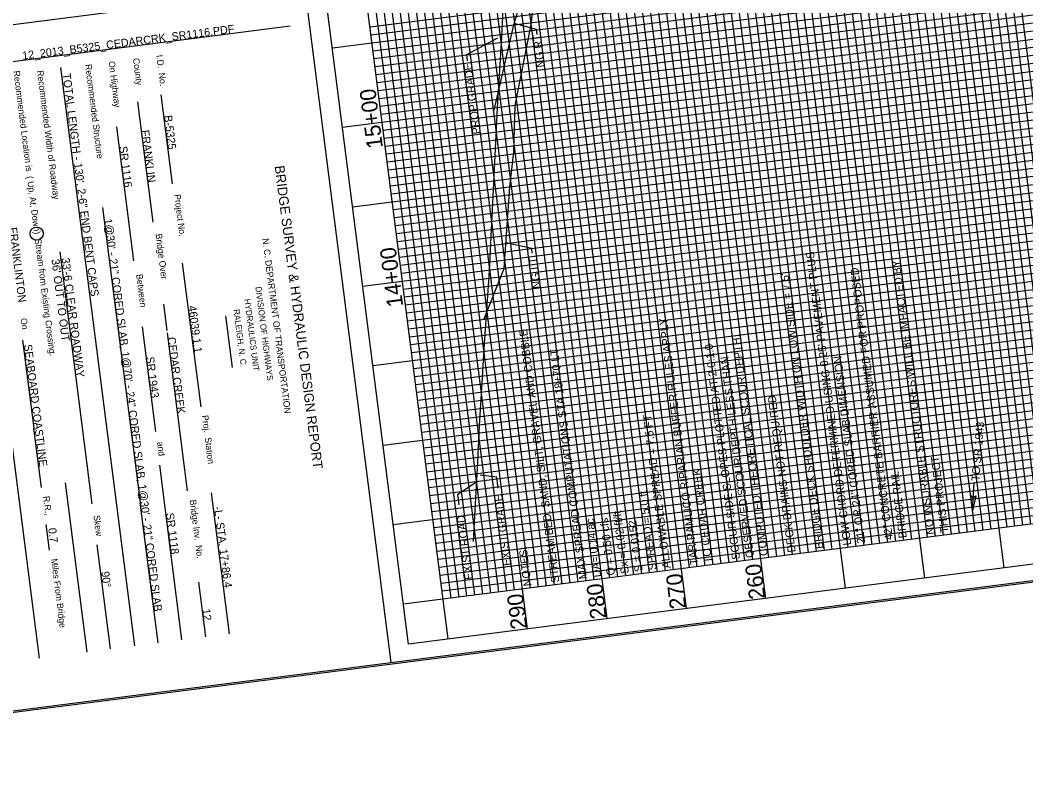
# Model space of a CAD drawing. Extents: x 2166991 to 2168413, y 842679 to 844296.
# Drawn here: x 2167468 to 2168096, y 842679 to 843150 of the extents above; entities that cross this region are included whole.
import ezdxf

# ---------------------------------------------------------------- set-up
doc = ezdxf.new("R2010")
doc.units = 0
for name, color, linetype in [('Exist Horizontal Alignment', 7, 'Continuous'), ('Exist Hydrographic Natural Ground Left', 7, 'Continuous'), ('Exist Hydrographic Natural Ground Right', 7, 'Continuous'), ('Old_Level_46', 7, 'Continuous'), ('Old_Level_61', 7, 'Continuous'), ('Prop Plan Preparation Cover Label', 7, 'Continuous'), ('Prop Plan Preparation Elevation Label', 7, 'Continuous'), ('Prop Plan Preparation Sheet Bridge Report Limited Study CELL', 7, 'Continuous'), ('Prop Plan Preparation Station Label', 7, 'Continuous'), ('Prop Plan Preparation Table Performance Curve CELL', 7, 'Continuous'), ('Sheet Plot Border Outside CELL', 7, 'Continuous'), ('Typical Terminator CELL', 7, 'Continuous')]:
    doc.layers.add(name, color=color, linetype=linetype)

msp = doc.modelspace()

# ---------------------------------------------------------------- linework, layer by layer
at = {"layer": 'Exist Horizontal Alignment'}
msp.add_lwpolyline([(2167751.39, 842824.91), (2167752.39, 842844.74), (2167753.95, 842874.72), (2167755.15, 842897.27), (2167757.06, 842927.31), (2167757.92, 842945.41), (2167760.09, 842975.47), (2167761.25, 842993.97), (2167762.76, 843023.98), (2167763.76, 843044.55), (2167765.23, 843074.51), (2167766.29, 843095.78), (2167768.15, 843125.8), (2167769.02, 843139.96), (2167770.48, 843169.95), (2167771.39, 843188.46), (2167770.67, 843218.15), (2167770.25, 843236.07), (2167768.33, 843265.68), (2167767.02, 843285.86), (2167763.97, 843315.19), (2167760.56, 843343.94)], dxfattribs=at)
at = {"layer": 'Exist Hydrographic Natural Ground Left'}
msp.add_lwpolyline([(2167757.79, 842963.56), (2167770.55, 842995.45), (2167773.98, 843046.3), (2167776.61, 843068.3), (2167777.35, 843097.13), (2167787.62, 843148.85), (2167792.18, 843199.84), (2167793.61, 843214.01), (2167797.76, 843250.96), (2167815.06, 843303.58), (2167817.99, 843332.01), (2167815.17, 843366.59)], dxfattribs=at)
at = {"layer": 'Exist Hydrographic Natural Ground Right'}
msp.add_lwpolyline([(2167764.31, 843094.3), (2167776.57, 843147.44), (2167792.18, 843199.84), (2167810.26, 843216.13), (2167772.9, 843247.78)], dxfattribs=at)
at = {"layer": 'Old_Level_46'}
for points in [[(2167791.01, 843141.49), (2167790.62, 843144.55), (2167776.78, 843148.24)], [(2167747.61, 843125.02), (2167747.11, 843128.93), (2167766.47, 843139.45)], [(2167788.04, 843005.03), (2167787.67, 843007.92), (2167771.61, 843011.4)], [(2167742.33, 842847.83), (2167741.48, 842854.49), (2167753.3, 842862.19)], [(2167766.83, 842858.38), (2167765.98, 842865.05), (2167755.49, 842866.42)]]:
    msp.add_lwpolyline(points, dxfattribs=at)
at = {"layer": 'Old_Level_61'}
msp.add_line((2168062.86, 842844.16), (2168064.07, 842861.57), dxfattribs=at)
at = {"layer": 'Prop Plan Preparation Cover Label'}
msp.add_circle((2167478.55, 843017.15), 4.12, dxfattribs=at)
at = {"layer": 'Prop Plan Preparation Sheet Bridge Report Limited Study CELL'}
for p, q in [((2168132.34, 842814.84), (2167973.96, 844054.76)), ((2168082.74, 842808.5), (2167924.37, 844048.43)), ((2168033.15, 842802.17), (2167874.77, 844042.09)), ((2167983.55, 842795.83), (2167825.17, 844035.76)), ((2167933.95, 842789.5), (2167775.57, 844029.42)), ((2168124.21, 842839), (2167972.17, 844029.33)), ((2168134.13, 842840.27), (2167982.09, 844030.6)), ((2167884.35, 842783.16), (2167725.98, 844023.09)), ((2168074.61, 842832.67), (2167922.57, 844023)), ((2168084.53, 842833.93), (2167932.49, 844024.26)), ((2168089.49, 842834.57), (2167937.45, 844024.9)), ((2168094.45, 842835.2), (2167942.41, 844025.53)), ((2168099.41, 842835.83), (2167947.37, 844026.16)), ((2168104.37, 842836.47), (2167952.33, 844026.8)), ((2168109.33, 842837.1), (2167957.29, 844027.43)), ((2168114.29, 842837.73), (2167962.25, 844028.06)), ((2168119.25, 842838.37), (2167967.21, 844028.7)), ((2167834.76, 842776.83), (2167676.38, 844016.75)), ((2168025.02, 842826.33), (2167872.98, 844016.66)), ((2168034.94, 842827.6), (2167882.9, 844017.93)), ((2168039.9, 842828.23), (2167887.86, 844018.56)), ((2168044.86, 842828.87), (2167892.82, 844019.19)), ((2168049.82, 842829.5), (2167897.78, 844019.83)), ((2168054.78, 842830.13), (2167902.74, 844020.46)), ((2168059.74, 842830.77), (2167907.69, 844021.1)), ((2168064.7, 842831.4), (2167912.65, 844021.73)), ((2168069.66, 842832.03), (2167917.61, 844022.36)), ((2167538.09, 844014.21), (2167699.63, 842749.49)), ((2167538.09, 844014.21), (2167699.63, 842749.49)), ((2167785.16, 842770.49), (2167626.78, 844010.42)), ((2167985.34, 842821.26), (2167833.3, 844011.59)), ((2167990.3, 842821.9), (2167838.26, 844012.23)), ((2167995.26, 842822.53), (2167843.22, 844012.86)), ((2168000.22, 842823.16), (2167848.18, 844013.49)), ((2168005.18, 842823.8), (2167853.14, 844014.13)), ((2168010.14, 842824.43), (2167858.1, 844014.76)), ((2168015.1, 842825.06), (2167863.06, 844015.39)), ((2168020.06, 842825.7), (2167868.02, 844016.03)), ((2167935.74, 842814.93), (2167783.7, 844005.26)), ((2167940.7, 842815.56), (2167788.66, 844005.89)), ((2167945.66, 842816.2), (2167793.62, 844006.52)), ((2167950.62, 842816.83), (2167798.58, 844007.16)), ((2167955.58, 842817.46), (2167803.54, 844007.79)), ((2167960.54, 842818.1), (2167808.5, 844008.43)), ((2167965.5, 842818.73), (2167813.46, 844009.06)), ((2167970.46, 842819.36), (2167818.42, 844009.69)), ((2167975.42, 842820), (2167823.38, 844010.33)), ((2167710.76, 842760.99), (2167552.39, 844000.92)), ((2167735.56, 842764.16), (2167577.19, 844004.08)), ((2167886.15, 842808.59), (2167734.11, 843998.92)), ((2167891.11, 842809.23), (2167739.06, 843999.56)), ((2167896.07, 842809.86), (2167744.02, 844000.19)), ((2167901.03, 842810.49), (2167748.98, 844000.82)), ((2167905.98, 842811.13), (2167753.94, 844001.46)), ((2167910.94, 842811.76), (2167758.9, 844002.09)), ((2167915.9, 842812.39), (2167763.86, 844002.72)), ((2167920.86, 842813.03), (2167768.82, 844003.36)), ((2167925.82, 842813.66), (2167773.78, 844003.99)), ((2167836.55, 842802.26), (2167684.51, 843992.59)), ((2167841.51, 842802.89), (2167689.47, 843993.22)), ((2167846.47, 842803.53), (2167694.43, 843993.85)), ((2167851.43, 842804.16), (2167699.39, 843994.49)), ((2167856.39, 842804.79), (2167704.35, 843995.12)), ((2167861.35, 842805.43), (2167709.31, 843995.76)), ((2167866.31, 842806.06), (2167714.27, 843996.39)), ((2167871.27, 842806.69), (2167719.23, 843997.02)), ((2167876.23, 842807.33), (2167724.19, 843997.66)), ((2167786.95, 842795.92), (2167634.91, 843986.25)), ((2167791.91, 842796.56), (2167639.87, 843986.89)), ((2167796.87, 842797.19), (2167644.83, 843987.52)), ((2167801.83, 842797.82), (2167649.79, 843988.15)), ((2167806.79, 842798.46), (2167654.75, 843988.79)), ((2167811.75, 842799.09), (2167659.71, 843989.42)), ((2167816.71, 842799.72), (2167664.67, 843990.05)), ((2167821.67, 842800.36), (2167669.63, 843990.69)), ((2167826.63, 842800.99), (2167674.59, 843991.32)), ((2167737.35, 842789.59), (2167585.31, 843979.92)), ((2167742.31, 842790.22), (2167590.27, 843980.55)), ((2167747.27, 842790.86), (2167595.23, 843981.18)), ((2167752.23, 842791.49), (2167600.19, 843981.82)), ((2167757.19, 842792.12), (2167605.15, 843982.45)), ((2167762.15, 842792.76), (2167610.11, 843983.09)), ((2167767.11, 842793.39), (2167615.07, 843983.72)), ((2167772.07, 842794.02), (2167620.03, 843984.35)), ((2167777.03, 842794.66), (2167624.99, 843984.99)), ((2168182.75, 843209.4), (2167686.78, 843146.05)), ((2168183.39, 843204.44), (2167687.42, 843141.09)), ((2168184.02, 843199.48), (2167663.25, 843132.97)), ((2168184.65, 843194.53), (2167688.68, 843131.17)), ((2168185.29, 843189.57), (2167689.32, 843126.21)), ((2168185.92, 843184.61), (2167689.95, 843121.26)), ((2168186.55, 843179.65), (2167690.58, 843116.3)), ((2167100.22, 843101.38), (2167645.78, 843171.06)), ((2168187.19, 843174.69), (2167691.22, 843111.34)), ((2168187.82, 843169.73), (2167691.85, 843106.38)), ((2168188.45, 843164.77), (2167692.48, 843101.42)), ((2168189.09, 843159.81), (2167693.12, 843096.46)), ((2168189.72, 843154.85), (2167693.75, 843091.5)), ((2167458.71, 843124.09), (2167636.89, 843146.84)), ((2168190.36, 843149.89), (2167669.59, 843083.37)), ((2168190.99, 843144.93), (2167695.02, 843081.58)), ((2168191.62, 843139.97), (2167695.65, 843076.62)), ((2168192.26, 843135.01), (2167696.29, 843071.66)), ((2168192.89, 843130.05), (2167696.92, 843066.7)), ((2168193.52, 843125.09), (2167697.55, 843061.74)), ((2167493.43, 843120.82), (2167539.55, 842759.79)), ((2168194.16, 843120.13), (2167698.19, 843056.78)), ((2168194.79, 843115.17), (2167698.82, 843051.82)), ((2168195.42, 843110.21), (2167699.45, 843046.86)), ((2167556.1, 843103.79), (2167563.18, 843048.33)), ((2168196.69, 843100.29), (2167675.92, 843033.77)), ((2168196.06, 843105.25), (2167700.09, 843041.9)), ((2167541.52, 843099.51), (2167551.12, 843024.38)), ((2168197.32, 843095.33), (2167701.35, 843031.98)), ((2168197.96, 843090.37), (2167701.99, 843027.02)), ((2167528.4, 843083.87), (2167539.08, 843000.26)), ((2168198.59, 843085.41), (2167702.62, 843022.06)), ((2168199.22, 843080.45), (2167703.25, 843017.1)), ((2168199.86, 843075.49), (2167703.89, 843012.14)), ((2168200.49, 843070.53), (2167704.52, 843007.18)), ((2168201.13, 843065.57), (2167705.15, 843002.22)), ((2167440.83, 843059.14), (2167480.03, 842752.21)), ((2168201.76, 843060.61), (2167705.79, 842997.26)), ((2168203.03, 843050.69), (2167682.26, 842984.18)), ((2168202.39, 843055.65), (2167706.42, 842992.3)), ((2168203.66, 843045.73), (2167707.69, 842982.38)), ((2168204.29, 843040.77), (2167708.32, 842977.42)), ((2167519.71, 843033.5), (2167543.21, 842849.5)), ((2168204.93, 843035.81), (2167708.96, 842972.46)), ((2168205.56, 843030.85), (2167709.59, 842967.5)), ((2168206.19, 843025.9), (2167710.22, 842962.54)), ((2168206.83, 843020.94), (2167710.86, 842957.58)), ((2168207.46, 843015.98), (2167711.49, 842952.63)), ((2167493.01, 843005.77), (2167513.09, 842848.51)), ((2168208.09, 843011.02), (2167712.12, 842947.67)), ((2168208.73, 843006.06), (2167712.76, 842942.71)), ((2168209.36, 843001.1), (2167688.59, 842934.58)), ((2167569.51, 842998.77), (2167580.98, 842908.99)), ((2168209.99, 842996.14), (2167714.02, 842932.79)), ((2168210.63, 842991.18), (2167714.66, 842927.83)), ((2168211.26, 842986.22), (2167715.29, 842922.87)), ((2168211.89, 842981.26), (2167715.92, 842917.91)), ((2168212.53, 842976.3), (2167716.56, 842912.95)), ((2167557.66, 842973.2), (2167559.77, 842956.66)), ((2168213.16, 842971.34), (2167717.19, 842907.99)), ((2167596.41, 842965.95), (2167600.55, 842933.52)), ((2167596.41, 842965.95), (2167600.55, 842933.52)), ((2167596.41, 842965.95), (2167600.55, 842933.52)), ((2168213.8, 842966.38), (2167717.82, 842903.03)), ((2167544.34, 842959.06), (2167552.7, 842893.63)), ((2168214.43, 842961.42), (2167718.46, 842898.07)), ((2168215.06, 842956.46), (2167719.09, 842893.11)), ((2167469.79, 842950.77), (2167476.83, 842895.65)), ((2167559.96, 842955.2), (2167572.55, 842856.59)), ((2168215.7, 842951.5), (2167694.93, 842884.98)), ((2168216.33, 842946.54), (2167720.36, 842883.19)), ((2168216.96, 842941.58), (2167720.99, 842878.23)), ((2168217.6, 842936.62), (2167721.63, 842873.27)), ((2168218.23, 842931.66), (2167722.26, 842868.31)), ((2168218.86, 842926.7), (2167722.89, 842863.35)), ((2168219.5, 842921.74), (2167723.53, 842858.39)), ((2168220.13, 842916.78), (2167724.16, 842853.43)), ((2168220.76, 842911.82), (2167724.79, 842848.47)), ((2168221.4, 842906.86), (2167725.43, 842843.51)), ((2168222.03, 842901.9), (2167701.26, 842835.38)), ((2167481.55, 842858.68), (2167476.81, 842895.82)), ((2168222.66, 842896.94), (2167726.69, 842833.59)), ((2168223.3, 842891.98), (2167727.33, 842828.63)), ((2168223.93, 842887.02), (2167727.96, 842823.67)), ((2168224.56, 842882.06), (2167728.59, 842818.71)), ((2168225.2, 842877.1), (2167729.23, 842813.75)), ((2167569.31, 842763.59), (2167555.38, 842872.65)), ((2168225.83, 842872.14), (2167729.86, 842808.79)), ((2167496.3, 842861.59), (2167509.79, 842755.99)), ((2168226.47, 842867.18), (2167730.49, 842803.83)), ((2168227.1, 842862.22), (2167731.13, 842798.87)), ((2167599.07, 842767.39), (2167587.82, 842855.42)), ((2168227.73, 842857.27), (2167731.76, 842793.91)), ((2167554.43, 842761.69), (2167543.24, 842849.25)), ((2168228.37, 842852.31), (2167707.6, 842785.79)), ((2167486.56, 842819.5), (2167484.49, 842835.66)), ((2168231.53, 842827.51), (2167710.76, 842760.99)), ((2167524.67, 842757.89), (2167516.36, 842822.91)), ((2167584.19, 842765.5), (2167579.83, 842799.62))]:
    msp.add_line(p, q, dxfattribs=at)
msp.add_lwpolyline([(2166992.52, 843944.53), (2167154.06, 842679.8), (2168245.2, 842819.17), (2168083.66, 844083.9)], close=True, dxfattribs=at)
at = {"layer": 'Sheet Plot Border Outside CELL'}
msp.add_lwpolyline([(2168246.32, 842818.31), (2168084.52, 844085.01), (2166991.4, 843945.39), (2167153.2, 842678.68)], close=True, dxfattribs=at)
at = {"layer": 'Typical Terminator CELL'}
msp.add_lwpolyline([(2168065.12, 842853.4), (2168062.86, 842844.16), (2168061.85, 842853.68), (2168063.43, 842852.37)], close=True, dxfattribs=at)

# ---------------------------------------------------------------- texts
at = {"layer": 'Old_Level_46'}
for s, p in [('NG RT ', (2167795.88, 843121.2)), ('PROP GRADE', (2167755.75, 843079.52)), ('NG LT', (2167793.31, 842983.17)), ('EXIST GRADE', (2167774.87, 842810.09)), ('EXIST ROAD', (2167750.94, 842801.47))]:
    msp.add_text(s, height=5, rotation=97.27898, dxfattribs=at).set_placement(p)
at = {"layer": 'Old_Level_61'}
msp.add_text('TO SR 1943', height=5, rotation=85.1501, dxfattribs=at).set_placement((2168067.18, 842862.53))
at = {"layer": 'Prop Plan Preparation Cover Label'}
for s, rotation, p in [('12_2013_B5325_CEDARCRK_SR1116.PDF', 7.27898, (2167469.86, 843125.75)), ('TOTAL LENGTH - 130\', 2-6" END BENT CAPS', 277.27898, (2167494.72, 843116.98)), ('B-5325', 277.27898, (2167558.08, 843090.79)), ('FRANKLIN', 277.27898, (2167543.77, 843081.56)), ('SR 1116', 277.27898, (2167530.03, 843071.5)), ('1@30\' - 21" CORED SLAB, 1@70\' - 24" CORED SLAB, 1@30\' - 21" CORED SLAB', 277.27898, (2167520.66, 843026.25)), ('FRANKLINTON', 277.27898, (2167461.25, 843020.77)), ("36' OUT TO OUT", 277.27898, (2167487.76, 843001.01)), ("33'-6 CLEAR ROADWAY ", 277.27898, (2167494.06, 843001.82)), ('46039.1.1', 277.27898, (2167573.26, 842971.95)), ('CEDAR CREEK', 277.27898, (2167560.28, 842952.33)), ('SEABOARD COASTLINE', 277.27898, (2167470.58, 842947.77)), ('SR 1943', 277.27898, (2167546.81, 842940.1)), ('SR 1118', 277.27898, (2167559.27, 842842.57)), ('-L- STA. 17+86.4', 277.27898, (2167589.27, 842846.55)), ('0.7', 277.27898, (2167485.75, 842833.17)), ('90%%d', 277.27898, (2167518.85, 842806.03)), ('12', 277.27898, (2167581.94, 842782.72))]:
    msp.add_text(s, height=5, rotation=rotation, dxfattribs=at).set_placement(p)
at = {"layer": 'Prop Plan Preparation Elevation Label'}
for s, p in [('260', (2167933.55, 842789.5)), ('270', (2167884.14, 842783.44)), ('280', (2167834.49, 842777.2)), ('290', (2167784.86, 842770.81))]:
    msp.add_text(s, height=10, rotation=97.27898, dxfattribs=at).set_placement(p)
at = {"layer": 'Prop Plan Preparation Sheet Bridge Report Limited Study CELL'}
for s, height, p in [('County', 4, (2167538.64, 843126.51)), ('I.D.  No.', 4, (2167553.24, 843128.53)), ('Recommended Location is  ( Up, At, Down)  Stream from Existing Crossing.', 4, (2167463.99, 843118.64)), ('Recommended Width of Roadway', 4, (2167478.73, 843118.81)), ('Recommended Structure', 4, (2167508.79, 843122.71)), ('On Highway', 4, (2167523.42, 843124.61)), ('BRIDGE SURVEY & HYDRAULIC DESIGN REPORT', 5.9999, (2167627.16, 843059.29)), ('Project No.', 4, (2167564.41, 843041.48)), ('Bridge Over', 4, (2167552.8, 843016.84)), ('N. C. DEPARTMENT OF TRANSPORTATION', 4, (2167619.46, 843014)), ('Between', 4, (2167540.67, 842991.63)), ('DIVISION OF HIGHWAYS', 3.7499, (2167615.1, 842983.86)), ('HYDRAULICS UNIT', 3.7499, (2167608.22, 842976.21)), ('RALEIGH, N. C.', 3.751, (2167601.46, 842969.76)), ('On', 4, (2167468.48, 842964.19)), ('Proj.  Station', 4, (2167581.72, 842903.61)), ('and', 4, (2167553.71, 842886.97)), ('R.R.,', 4, (2167482.51, 842853.12)), ('Bridge Inv.  No.', 4, (2167574.09, 842850.78)), ('Skew', 4, (2167514.08, 842841.15)), ('Miles From Bridge', 4, (2167487.51, 842813.98))]:
    msp.add_text(s, height=height, rotation=277.27898, dxfattribs=at).set_placement(p)
at = {"layer": 'Prop Plan Preparation Station Label'}
for s, p in [('15+00', (2167694.79, 843070.92)), ('14+00', (2167707.44, 842971.95))]:
    msp.add_text(s, height=10, rotation=97.27898, dxfattribs=at).set_placement(p)
at = {"layer": 'Prop Plan Preparation Table Performance Curve CELL'}
for s, p in [("LOW CHORD DETERMINED USING 0.25' PAVEMENT PLUS", (2167987.27, 842822.9)), ('NO INSURABLE STRUCTURES WILL BE IMPACTED BY ', (2168039.35, 842829.55)), ('42" CONCRETE BARRIER ASSUMED FOR PROPOSED ', (2168013.31, 842826.23)), ("BRIDGE DECK SHOULDER WIDTH ON LOW SIDE = 7.5'", (2167969.91, 842820.69)), ('TAR-PAMLICO RIPARIAN BUFFER RULES APPLY', (2167891.79, 842810.71)), ('STREAM BED: SAND, SILT, GRAVEL AND COBBLE', (2167805, 842799.62)), ('COMPUTED THEORETICAL SCOUR DEPTH.', (2167935.19, 842816.25)), ('MAX SPREAD COMPUTATIONS STA 18+70 LT', (2167822.36, 842801.84)), ('SCOUR SIDE SLOPES PLOTTED AT 2.0:1.0', (2167917.83, 842814.03)), ('OBSERVED SCOUR DEPTH LESS THAN ', (2167926.51, 842815.14)), ('21" OR 24" CORED SLAB DIMENSION', (2167995.95, 842824.01)), ('DECK DRAINS NOT REQUIRED', (2167952.55, 842818.47)), ('ALLOWABLE SPREAD = 7.5 FT', (2167874.44, 842808.49)), ('THIS PROJECT', (2168048.02, 842830.66)), ('TO CEDAR CREEK', (2167900.47, 842811.82)), ('BRIDGE RAIL', (2168021.99, 842827.34)), ('SPREAD = 5.0 ft', (2167865.76, 842807.38)), ('Sx = 0.02 ft/ft', (2167848.4, 842805.16)), ('DA= 0.14 ac', (2167831.04, 842802.95)), ('Q = 0.50 cfs', (2167839.72, 842804.06)), ('S = 0.0152', (2167857.08, 842806.27)), ('NOTES:', (2167787.64, 842797.4))]:
    msp.add_text(s, height=5, rotation=97.27898, dxfattribs=at).set_placement(p)

doc.saveas('drawing.dxf')
